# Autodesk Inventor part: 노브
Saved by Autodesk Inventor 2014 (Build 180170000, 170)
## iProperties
Created: 2025-02
Part Number: 노브
Material: 일반
Document SubType Name: Modeling
Designer: dg
Density: 1 g/cm^3
Appearance: 기본값
Author: dg
Author: jhkim
Creation Date: 2025-02-05
Sending System: Autodesk Inventor 2025
Preprocessor: ST-DEVELOPER v20
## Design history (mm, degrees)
node "노브1"
node "솔리드1"
node "기준1"
